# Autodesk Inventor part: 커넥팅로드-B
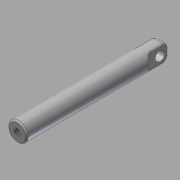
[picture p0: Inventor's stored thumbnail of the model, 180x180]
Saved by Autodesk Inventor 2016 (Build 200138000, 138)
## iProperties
Created: 2018-01
Part Number: 커넥팅로드-B
Material: 강철, 연강
Document SubType Name: Modeling
Designer: mduedu
Density: 7.86 g/cm^3
Appearance: 강철
Mass: 14.5817 g
Surface Area: 12.9188 cm^2
Volume: 1.85518 cm^3
Author: mduedu
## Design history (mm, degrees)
sketch "스케치1"
  geometry: C1 r 3.5 at (0, 0); 1 further point
  constraints: 1 centre point, 1 coincident
  dimensions: "d0" = 7 diameter of C1
extrude "돌출1" new body sketch "스케치1" distance "d1" = 53; taper "d2" = 0 deg
node "작업 평면1"
sketch "스케치2"
  geometry: L1 (-3.5, 0)-(3.5, 0) reference; L2 (4, 4)-(4, 0); L3 (4, 0)-(-4, 0); L4 (-4, 0)-(-4, 4); A1 r 4 centre (0, 4) between (4, 4) and (-4, 4); 2 further points
  constraints: 6 end point, 2 perpendicular, 2 point on circle, 2 tangent, 1 centre point, 1 collinear, 1 midpoint, 1 vertical, 1 vertical alignment
  dimensions: "d4" = 8 diameter of A1; "d5" = 4 distance from line of A1.centre L1
extrude "돌출2" cut sketch "스케치2" stored distance "d6" = 53; taper "d7" = 0 deg
fillet "모깎기1" dims "d8" = 2
fillet "모깎기2" dims "d9" = 0.5
fillet "모깎기3" dims "d10" = 0.5
sketch "스케치3"
  geometry: C1 r 1.75 at (0, 3); 1 further point
  constraints: 1 centre point, 1 vertical alignment
  dimensions: "d11" = 3.5 diameter of C1; "d12" = 3 distance of point (0, 0) C1.centre
extrude "돌출3" cut sketch "스케치3" stored distance "d13" = 53; taper "d14" = 0 deg
chamfer "모따기1" distance "d15" = 0.5; stored, may be unused: second distance "d16" = 2, angle "d17" = 45 deg
sketch "스케치4"
  geometry: 1 further point
hole "구멍1" sketch "스케치4" at (0, 0) diameter "d18" = 2.459; stored, may be unused: countersink angle "d22" = 90 deg, drill point angle "d24" = 120 deg; dims "d19" = 6.9, "d20" = 4, "d21" = 2, "d23" = 8.4
node "솔리드1"
mirror "대칭1"
other parameters: "d3" = 2
